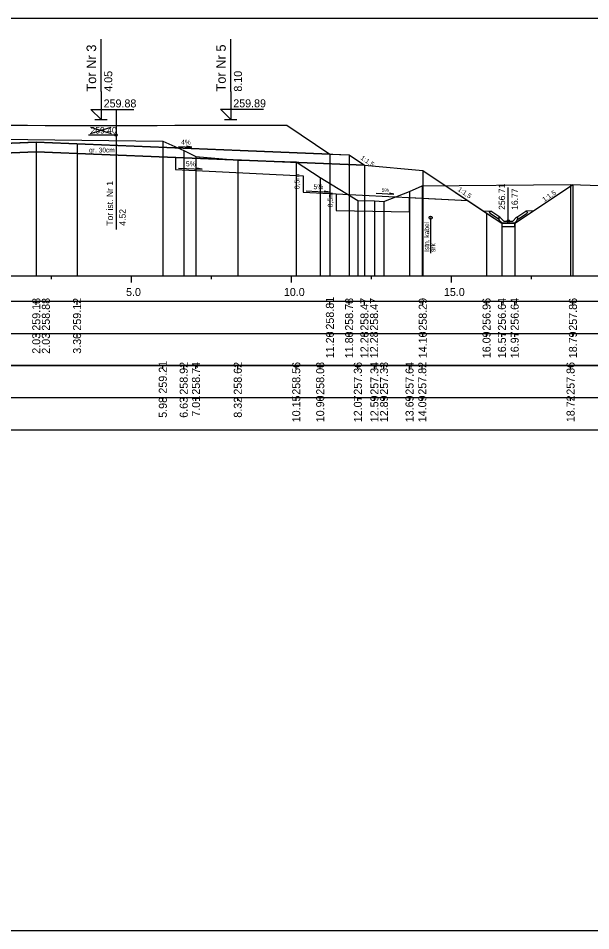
# Model space of a CAD drawing. Extents: x 6516023 to 6560129, y 5513077 to 5529206.
# Drawn here: x 6516406.98 to 6516424.86, y 5514551.66 to 5514580.16 of the extents above; entities that cross this region are included whole.
import ezdxf

# ---------------------------------------------------------------- set-up
doc = ezdxf.new("R2010")
doc.units = 0
for name, color, linetype in [('IR_default', 7, 'Continuous'), ('TOR_PRZEK_P-kable', 7, 'Continuous'), ('TOR_PRZEK_P-komponent', 7, 'Continuous'), ('TOR_PRZEK_P-odwodnienie', 7, 'Continuous'), ('TOR_PRZEK_P-opisy', 7, 'Continuous'), ('TOR_PRZEK_P-schodkowanie+wymiana', 7, 'Continuous'), ('TOR_PRZEK_P-tabelka istniejace', 7, 'Continuous'), ('TOR_PRZEK_P-tabelka projektowane', 7, 'Continuous'), ('TOR_PRZEK_P-teren istniejacy', 7, 'Continuous'), ('TOR_PRZEK_P-tory istniejace', 7, 'Continuous'), ('TOR_PRZEK_P-tory projektowane', 7, 'Continuous'), ('TOR_PRZEK_P-uklad odniesienia', 7, 'Continuous'), ('TOR_PRZEK_P-warstwa ochronna I', 7, 'Continuous'), ('TOR_PRZEK_P-warstwa ochronna II', 7, 'Continuous'), ('TOR_PS_T-skarpy projektowane', 7, 'Continuous'), ('TOR_RAMKI-ramka+tabelka 1', 7, 'Continuous')]:
    doc.layers.add(name, color=color, linetype=linetype)

msp = doc.modelspace()

# ---------------------------------------------------------------- linework, layer by layer
at = {"layer": 'IR_default'}
msp.add_lwpolyline([(6516405.513, 5514576.813), (6516407.263, 5514576.813), (6516407.813, 5514576.811), (6516409.563, 5514576.811), (6516411.313, 5514576.811), (6516411.863, 5514576.814), (6516415.363, 5514576.814), (6516416.712, 5514575.915), (6516417.313, 5514575.891), (6516417.792, 5514575.572), (6516419.613, 5514575.399), (6516422.086, 5514573.751), (6516422.486, 5514573.751), (6516423.077, 5514574.145), (6516424.305, 5514574.964)], dxfattribs=at)
at = {"layer": 'TOR_PRZEK_P-kable'}
msp.add_line((6516419.859, 5514573.929), (6516419.859, 5514572.819), dxfattribs=at)
msp.add_circle((6516419.859, 5514573.929), 0.05, dxfattribs=at)
at = {"layer": 'TOR_PRZEK_P-komponent'}
for points in [[(6516399.663, 5514576.813), (6516401.413, 5514576.813), (6516400.159, 5514576.813), (6516403.163, 5514576.813), (6516403.763, 5514576.813), (6516405.513, 5514576.813), (6516407.263, 5514576.813), (6516407.813, 5514576.811), (6516409.563, 5514576.811), (6516411.313, 5514576.811), (6516411.863, 5514576.814), (6516415.363, 5514576.814), (6516416.712, 5514575.915), (6516407.538, 5514576.282), (6516398.313, 5514575.913)], [(6516397.713, 5514575.889), (6516407.538, 5514576.282), (6516417.313, 5514575.891), (6516417.792, 5514575.572), (6516407.538, 5514575.982), (6516397.234, 5514575.57)]]:
    msp.add_lwpolyline(points, close=True, dxfattribs=at)
at = {"layer": 'TOR_PRZEK_P-odwodnienie'}
for p, q in [((6516422.286, 5514573.821), (6516422.286, 5514574.865)), ((6516421.977, 5514573.88), (6516421.715, 5514574.054)), ((6516422.021, 5514573.947), (6516421.741, 5514574.134)), ((6516421.988, 5514573.897), (6516421.977, 5514573.88)), ((6516421.978, 5514573.916), (6516422.026, 5514573.94)), ((6516422.021, 5514573.947), (6516422.013, 5514573.934)), ((6516422.146, 5514573.821), (6516422.026, 5514573.94)), ((6516422.426, 5514573.821), (6516422.546, 5514573.94)), ((6516422.546, 5514573.94), (6516422.593, 5514573.916)), ((6516422.55, 5514573.947), (6516422.831, 5514574.134)), ((6516422.55, 5514573.947), (6516422.559, 5514573.934)), ((6516422.583, 5514573.897), (6516422.595, 5514573.88)), ((6516422.595, 5514573.88), (6516422.856, 5514574.054)), ((6516422.096, 5514573.751), (6516422.476, 5514573.751)), ((6516422.146, 5514573.821), (6516422.426, 5514573.821))]:
    msp.add_line(p, q, dxfattribs=at)
for points in [[(6516421.494, 5514574.145), (6516421.741, 5514574.134)], [(6516421.69, 5514574.107), (6516421.741, 5514574.134)], [(6516421.69, 5514574.107), (6516421.715, 5514574.054)], [(6516422.013, 5514573.934), (6516421.977, 5514573.916)], [(6516421.977, 5514573.916), (6516421.988, 5514573.897)], [(6516422.026, 5514573.821), (6516421.978, 5514573.916)], [(6516422.546, 5514573.821), (6516422.593, 5514573.916)], [(6516422.559, 5514573.934), (6516422.594, 5514573.916)], [(6516422.594, 5514573.916), (6516422.583, 5514573.897)], [(6516423.077, 5514574.145), (6516422.831, 5514574.134)], [(6516422.881, 5514574.107), (6516422.831, 5514574.134)], [(6516422.881, 5514574.107), (6516422.856, 5514574.054)], [(6516422.096, 5514573.751), (6516422.026, 5514573.821)], [(6516422.486, 5514573.751), (6516422.086, 5514573.751), (6516422.086, 5514573.651), (6516422.486, 5514573.651), (6516422.486, 5514573.751)], [(6516422.476, 5514573.751), (6516422.546, 5514573.821)]]:
    msp.add_lwpolyline(points, dxfattribs=at)
msp.add_circle((6516422.286, 5514573.821), 0.035, dxfattribs=at)
at = {"layer": 'TOR_PRZEK_P-opisy'}
msp.add_lwpolyline([(6516411.985, 5514576.147), (6516412.403, 5514576.128), (6516412.235, 5514576.157)], dxfattribs=at)
at = {"layer": 'TOR_PRZEK_P-schodkowanie+wymiana'}
for p, q in [((6516411.889, 5514575.808), (6516411.889, 5514575.435)), ((6516411.889, 5514575.435), (6516415.882, 5514575.235)), ((6516415.873, 5514575.236), (6516415.873, 5514574.721)), ((6516415.873, 5514574.721), (6516416.903, 5514574.669)), ((6516416.912, 5514574.669), (6516416.912, 5514574.154)), ((6516416.912, 5514574.669), (6516421.017, 5514574.463))]:
    msp.add_line(p, q, dxfattribs=at)
msp.add_lwpolyline([(6516416.912, 5514574.154), (6516419.2, 5514574.11), (6516419.2, 5514574.554), (6516421.017, 5514574.463)], dxfattribs=at)
at = {"layer": 'TOR_PRZEK_P-tabelka istniejace'}
for p, q in [((6516411.492, 5514569.206), (6516411.492, 5514569.306)), ((6516412.145, 5514569.206), (6516412.145, 5514569.306)), ((6516412.527, 5514569.206), (6516412.527, 5514569.306)), ((6516413.835, 5514569.206), (6516413.835, 5514569.306)), ((6516415.661, 5514569.206), (6516415.661, 5514569.306)), ((6516416.409, 5514569.206), (6516416.409, 5514569.306)), ((6516417.585, 5514569.206), (6516417.585, 5514569.306)), ((6516418.103, 5514569.206), (6516418.103, 5514569.306)), ((6516418.402, 5514569.206), (6516418.402, 5514569.306)), ((6516419.2, 5514569.206), (6516419.2, 5514569.306)), ((6516419.599, 5514569.206), (6516419.599, 5514569.306)), ((6516424.231, 5514569.206), (6516424.231, 5514569.306)), ((6516364.663, 5514568.306), (6516443.463, 5514568.306)), ((6516411.492, 5514568.206), (6516411.492, 5514568.306)), ((6516412.145, 5514568.206), (6516412.145, 5514568.306)), ((6516412.527, 5514568.206), (6516412.527, 5514568.306)), ((6516413.835, 5514568.206), (6516413.835, 5514568.306)), ((6516415.661, 5514568.206), (6516415.661, 5514568.306)), ((6516416.409, 5514568.206), (6516416.409, 5514568.306)), ((6516417.585, 5514568.206), (6516417.585, 5514568.306)), ((6516418.103, 5514568.206), (6516418.103, 5514568.306)), ((6516418.402, 5514568.206), (6516418.402, 5514568.306)), ((6516419.2, 5514568.206), (6516419.2, 5514568.306)), ((6516419.599, 5514568.206), (6516419.599, 5514568.306)), ((6516424.231, 5514568.206), (6516424.231, 5514568.306))]:
    msp.add_line(p, q, dxfattribs=at)
for points in [[(6516411.492, 5514576.312), (6516411.492, 5514572.306), (6516411.492, 5514572.176), (6516411.492, 5514572.106)], [(6516412.145, 5514576.025), (6516412.145, 5514572.306), (6516412.145, 5514572.176), (6516412.145, 5514572.106)], [(6516412.527, 5514575.843), (6516412.527, 5514572.306), (6516412.527, 5514572.176), (6516412.527, 5514572.106)], [(6516413.835, 5514575.724), (6516413.835, 5514572.306), (6516413.835, 5514572.176), (6516413.835, 5514572.106)], [(6516415.661, 5514575.67), (6516415.661, 5514572.306), (6516415.661, 5514572.176), (6516415.661, 5514572.106)], [(6516416.409, 5514575.186), (6516416.409, 5514572.306), (6516416.409, 5514572.176), (6516416.409, 5514572.106)], [(6516419.2, 5514574.75), (6516419.2, 5514572.306), (6516419.2, 5514572.176), (6516419.2, 5514572.106)], [(6516419.599, 5514574.924), (6516419.599, 5514572.306), (6516419.599, 5514572.176), (6516419.599, 5514572.106)], [(6516424.231, 5514574.966), (6516424.231, 5514572.306), (6516424.231, 5514572.176), (6516424.231, 5514572.106)], [(6516417.585, 5514574.468), (6516417.585, 5514572.306), (6516417.585, 5514572.176), (6516417.585, 5514572.106)], [(6516418.103, 5514574.449), (6516418.103, 5514572.306), (6516418.103, 5514572.176), (6516418.103, 5514572.106)], [(6516418.402, 5514574.436), (6516418.402, 5514572.306), (6516418.402, 5514572.176), (6516418.402, 5514572.106)]]:
    msp.add_lwpolyline(points, dxfattribs=at)
msp.add_lwpolyline([(6516364.663, 5514569.306), (6516364.663, 5514567.306), (6516443.463, 5514567.306), (6516443.463, 5514569.306)], close=True, dxfattribs=at)
at = {"layer": 'TOR_PRZEK_P-tabelka projektowane'}
for p, q in [((6516407.538, 5514571.206), (6516407.538, 5514571.306)), ((6516408.813, 5514571.206), (6516408.813, 5514571.306)), ((6516416.712, 5514571.206), (6516416.712, 5514571.306)), ((6516417.313, 5514571.206), (6516417.313, 5514571.306)), ((6516417.792, 5514571.206), (6516417.792, 5514571.306)), ((6516419.613, 5514571.206), (6516419.613, 5514571.306)), ((6516421.606, 5514571.206), (6516421.606, 5514571.306)), ((6516422.086, 5514571.206), (6516422.086, 5514571.306)), ((6516422.486, 5514571.206), (6516422.486, 5514571.306)), ((6516424.305, 5514571.206), (6516424.305, 5514571.306)), ((6516364.663, 5514570.306), (6516443.463, 5514570.306)), ((6516407.538, 5514570.206), (6516407.538, 5514570.306)), ((6516408.813, 5514570.206), (6516408.813, 5514570.306)), ((6516416.712, 5514570.206), (6516416.712, 5514570.306)), ((6516417.313, 5514570.206), (6516417.313, 5514570.306)), ((6516417.792, 5514570.206), (6516417.792, 5514570.306)), ((6516419.613, 5514570.206), (6516419.613, 5514570.306)), ((6516421.606, 5514570.206), (6516421.606, 5514570.306)), ((6516422.086, 5514570.206), (6516422.086, 5514570.306)), ((6516422.486, 5514570.206), (6516422.486, 5514570.306)), ((6516424.305, 5514570.206), (6516424.305, 5514570.306))]:
    msp.add_line(p, q, dxfattribs=at)
for points in [[(6516407.538, 5514576.282), (6516407.538, 5514572.306), (6516407.538, 5514572.176), (6516407.538, 5514572.106)], [(6516408.813, 5514576.231), (6516408.813, 5514572.306), (6516408.813, 5514572.176), (6516408.813, 5514572.106)], [(6516407.538, 5514575.982), (6516407.538, 5514572.306), (6516407.538, 5514572.176), (6516407.538, 5514572.106)], [(6516416.712, 5514575.915), (6516416.712, 5514572.306), (6516416.712, 5514572.176), (6516416.712, 5514572.106)], [(6516417.313, 5514575.891), (6516417.313, 5514572.306), (6516417.313, 5514572.176), (6516417.313, 5514572.106)], [(6516417.792, 5514575.572), (6516417.792, 5514572.306), (6516417.792, 5514572.176), (6516417.792, 5514572.106)], [(6516419.613, 5514575.399), (6516419.613, 5514572.306), (6516419.613, 5514572.176), (6516419.613, 5514572.106)], [(6516424.305, 5514574.964), (6516424.305, 5514572.306), (6516424.305, 5514572.176), (6516424.305, 5514572.106)], [(6516421.606, 5514574.071), (6516421.606, 5514572.306), (6516421.606, 5514572.176), (6516421.606, 5514572.106)], [(6516422.086, 5514573.751), (6516422.086, 5514572.306), (6516422.086, 5514572.176), (6516422.086, 5514572.106)], [(6516422.486, 5514573.751), (6516422.486, 5514572.306), (6516422.486, 5514572.176), (6516422.486, 5514572.106)]]:
    msp.add_lwpolyline(points, dxfattribs=at)
msp.add_lwpolyline([(6516364.663, 5514571.306), (6516364.663, 5514569.306), (6516443.463, 5514569.306), (6516443.463, 5514571.306)], close=True, dxfattribs=at)
at = {"layer": 'TOR_PRZEK_P-teren istniejacy'}
msp.add_lwpolyline([(6516404.738, 5514576.396), (6516411.492, 5514576.312), (6516412.145, 5514576.025), (6516412.527, 5514575.843), (6516413.835, 5514575.724), (6516415.661, 5514575.67), (6516416.409, 5514575.186), (6516417.585, 5514574.468), (6516418.103, 5514574.449), (6516418.402, 5514574.436), (6516419.2, 5514574.75), (6516419.599, 5514574.924), (6516424.231, 5514574.966), (6516426.395, 5514574.89)], dxfattribs=at)
at = {"layer": 'TOR_PRZEK_P-tory istniejace'}
for p, q in [((6516410.031, 5514577.282), (6516410.031, 5514573.562)), ((6516409.232, 5514576.554), (6516409.883, 5514576.757)), ((6516409.232, 5514576.757), (6516409.883, 5514576.554)), ((6516410.032, 5514576.507), (6516409.166, 5514576.507))]:
    msp.add_line(p, q, dxfattribs=at)
msp.add_circle((6516410.032, 5514576.507), 0.035, dxfattribs=at)
at = {"layer": 'TOR_PRZEK_P-tory projektowane'}
for p, q in [((6516409.563, 5514577.869), (6516409.563, 5514579.501)), ((6516413.613, 5514577.872), (6516413.613, 5514579.504)), ((6516409.563, 5514577.869), (6516409.563, 5514576.991)), ((6516413.613, 5514577.872), (6516413.613, 5514576.994)), ((6516409.563, 5514576.991), (6516409.244, 5514577.31)), ((6516409.244, 5514577.31), (6516410.588, 5514577.31)), ((6516413.613, 5514576.994), (6516413.294, 5514577.313)), ((6516413.294, 5514577.313), (6516414.638, 5514577.313)), ((6516409.371, 5514576.991), (6516409.755, 5514576.991)), ((6516413.421, 5514576.994), (6516413.805, 5514576.994))]:
    msp.add_line(p, q, dxfattribs=at)
at = {"layer": 'TOR_PRZEK_P-uklad odniesienia'}
for p, q in [((6516368.463, 5514572.106), (6516443.463, 5514572.106)), ((6516408.013, 5514572.006), (6516408.013, 5514572.106)), ((6516410.513, 5514571.906), (6516410.513, 5514572.106)), ((6516413.013, 5514572.006), (6516413.013, 5514572.106)), ((6516415.513, 5514571.906), (6516415.513, 5514572.106)), ((6516418.013, 5514572.006), (6516418.013, 5514572.106)), ((6516420.513, 5514571.906), (6516420.513, 5514572.106)), ((6516423.013, 5514572.006), (6516423.013, 5514572.106))]:
    msp.add_line(p, q, dxfattribs=at)
at = {"layer": 'TOR_PRZEK_P-warstwa ochronna I'}
msp.add_lwpolyline([(6516397.234, 5514575.57), (6516407.538, 5514575.982), (6516417.792, 5514575.572)], dxfattribs=at)
at = {"layer": 'TOR_PRZEK_P-warstwa ochronna II'}
msp.add_lwpolyline([(6516387.53, 5514574.002), (6516391.061, 5514573.87), (6516391.673, 5514573.462), (6516392.423, 5514573.462), (6516393.109, 5514573.861), (6516395.413, 5514575.397), (6516397.234, 5514575.57), (6516397.713, 5514575.889), (6516398.313, 5514575.913), (6516406.263, 5514576.233), (6516407.538, 5514576.282), (6516408.813, 5514576.231), (6516416.712, 5514575.915), (6516417.313, 5514575.891), (6516417.792, 5514575.572), (6516419.613, 5514575.399), (6516421.606, 5514574.071), (6516422.086, 5514573.751), (6516422.486, 5514573.751), (6516424.305, 5514574.964)], dxfattribs=at)
at = {"layer": 'TOR_PS_T-skarpy projektowane'}
for points in [[(6516411.982, 5514575.479), (6516412.717, 5514575.44), (6516412.545, 5514575.47)], [(6516415.966, 5514574.765), (6516416.702, 5514574.725), (6516416.529, 5514574.756)], [(6516418.155, 5514574.695), (6516418.706, 5514574.665), (6516418.577, 5514574.688)]]:
    msp.add_lwpolyline(points, dxfattribs=at)
at = {"layer": 'TOR_RAMKI-ramka+tabelka 1'}
msp.add_lwpolyline([(6516362.013, 5514580.156), (6516609.513, 5514580.156), (6516609.513, 5514551.656), (6516362.013, 5514551.656)], close=True, dxfattribs=at)

# ---------------------------------------------------------------- texts
at = {"layer": 'TOR_PRZEK_P-kable'}
for s, height, p in [('Istn. kabel', 0.14999, (6516419.814, 5514572.855)), ('srk', 0.15, (6516420.008, 5514572.855))]:
    msp.add_text(s, height=height, rotation=90.0511, dxfattribs=at).set_placement(p)
at = {"layer": 'TOR_PRZEK_P-odwodnienie'}
for s, p in [('256.71', (6516422.186, 5514574.171)), ('16.77', (6516422.586, 5514574.171))]:
    msp.add_text(s, height=0.2, rotation=90, dxfattribs=at).set_placement(p)
at = {"layer": 'TOR_PRZEK_P-opisy'}
for s, rotation, p in [('4%', 359.8485, (6516412.064, 5514576.213)), ('1:1,5', 325.9299, (6516417.655, 5514575.764)), ('1:1,5', 325.9299, (6516420.691, 5514574.776)), ('1:1,5', 34.0701, (6516423.412, 5514574.414))]:
    msp.add_text(s, height=0.15, rotation=rotation, dxfattribs=at).set_placement(p)
at = {"layer": 'TOR_PRZEK_P-schodkowanie+wymiana'}
for p in [(6516415.762, 5514574.817), (6516416.801, 5514574.25)]:
    msp.add_text('0,5m', height=0.1545, rotation=90, dxfattribs=at).set_placement(p)
at = {"layer": 'TOR_PRZEK_P-tabelka istniejace'}
for s, p in [('259.21', (6516411.617, 5514568.433)), ('258.92', (6516412.27, 5514568.4)), ('258.74', (6516412.652, 5514568.399)), ('258.62', (6516413.96, 5514568.4)), ('258.56', (6516415.786, 5514568.398)), ('258.08', (6516416.534, 5514568.398)), ('257.36', (6516417.71, 5514568.398)), ('257.34', (6516418.228, 5514568.399)), ('257.33', (6516418.527, 5514568.398)), ('257.64', (6516419.325, 5514568.399)), ('257.82', (6516419.724, 5514568.4)), ('257.86', (6516424.356, 5514568.398)), ('5.98', (6516411.617, 5514567.677)), ('6.63', (6516412.27, 5514567.678)), ('7.01', (6516412.652, 5514567.712)), ('8.32', (6516413.96, 5514567.68)), ('10.15', (6516415.786, 5514567.537)), ('10.90', (6516416.534, 5514567.538)), ('12.07', (6516417.71, 5514567.538)), ('12.59', (6516418.228, 5514567.538)), ('12.89', (6516418.527, 5514567.538)), ('13.69', (6516419.325, 5514567.538)), ('14.09', (6516419.724, 5514567.538)), ('18.72', (6516424.356, 5514567.54))]:
    msp.add_text(s, height=0.25, rotation=90, dxfattribs=at).set_placement(p)
at = {"layer": 'TOR_PRZEK_P-tabelka projektowane'}
for s, p in [('259.18', (6516407.663, 5514570.398)), ('258.88', (6516407.963, 5514570.398)), ('259.12', (6516408.938, 5514570.4)), ('258.81', (6516416.837, 5514570.433)), ('258.78', (6516417.438, 5514570.398)), ('258.47', (6516417.917, 5514570.398)), ('258.47', (6516418.217, 5514570.398)), ('258.29', (6516419.738, 5514570.398)), ('256.96', (6516421.731, 5514570.398)), ('256.64', (6516422.211, 5514570.399)), ('256.64', (6516422.611, 5514570.399)), ('257.86', (6516424.43, 5514570.398)), ('2.03', (6516407.663, 5514569.678)), ('2.03', (6516407.963, 5514569.678)), ('3.30', (6516408.938, 5514569.678)), ('11.20', (6516416.837, 5514569.538)), ('11.80', (6516417.438, 5514569.538)), ('12.28', (6516417.917, 5514569.538)), ('12.28', (6516418.217, 5514569.538)), ('14.10', (6516419.738, 5514569.538)), ('16.09', (6516421.731, 5514569.538)), ('16.57', (6516422.211, 5514569.538)), ('16.97', (6516422.611, 5514569.538)), ('18.79', (6516424.43, 5514569.538))]:
    msp.add_text(s, height=0.25, rotation=90, dxfattribs=at).set_placement(p)
at = {"layer": 'TOR_PRZEK_P-tory istniejace'}
msp.add_text('259.40', height=0.2, dxfattribs=at).set_placement((6516409.232, 5514576.557))
for s, rotation, p in [('Tor ist. Nr 1', 90.0511, (6516409.938, 5514573.677)), ('4.52', 90, (6516410.332, 5514573.677))]:
    msp.add_text(s, height=0.2, rotation=rotation, dxfattribs=at).set_placement(p)
at = {"layer": 'TOR_PRZEK_P-tory projektowane'}
for s, height, p in [('Tor Nr 3', 0.3, (6516409.409, 5514577.863)), ('Tor Nr 5', 0.3, (6516413.459, 5514577.866)), ('4.05', 0.25, (6516409.913, 5514577.861)), ('8.10', 0.25, (6516413.963, 5514577.864))]:
    msp.add_text(s, height=height, rotation=90, dxfattribs=at).set_placement(p)
for s, p in [('259.88', (6516409.643, 5514577.371)), ('259.89', (6516413.693, 5514577.374))]:
    msp.add_text(s, height=0.25, dxfattribs=at).set_placement(p)
at = {"layer": 'TOR_PRZEK_P-uklad odniesienia'}
for s, p in [('5.0', (6516410.344, 5514571.481)), ('10.0', (6516415.274, 5514571.481)), ('15.0', (6516420.274, 5514571.481))]:
    msp.add_text(s, height=0.25, dxfattribs=at).set_placement(p)
at = {"layer": 'TOR_PRZEK_P-warstwa ochronna I'}
msp.add_text('gr. 30cm', height=0.15, dxfattribs=at).set_placement((6516409.187, 5514575.964))
at = {"layer": 'TOR_PS_T-skarpy projektowane'}
for height, p in [(0.1545, (6516412.214, 5514575.531)), (0.1545, (6516416.199, 5514574.817)), (0.1159, (6516418.329, 5514574.733))]:
    msp.add_text('5%', height=height, dxfattribs=at).set_placement(p)

doc.saveas('drawing.dxf')
